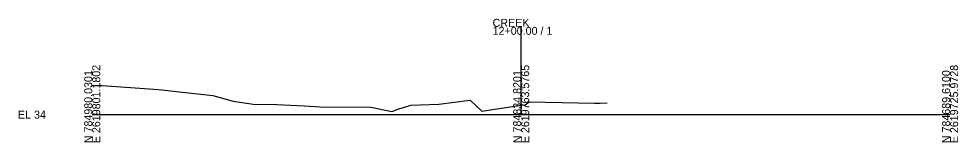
# Model space of a CAD drawing. Extents: x -26 to 303, y -10 to 5021.
# Drawn here: x -25.7 to 302.8, y 1490.3 to 1533.7 of the extents above; entities that cross this region are included whole.
import ezdxf

# ---------------------------------------------------------------- set-up
doc = ezdxf.new("R2010")
doc.units = 0
for name, color, linetype in [('RD_GPK_XS_Cell', 7, 'Continuous'), ('RD_XS_ExGround', 7, 'Continuous'), ('RD_XS_TX_Elev_EX', 7, 'Continuous')]:
    doc.layers.add(name, color=color, linetype=linetype)

msp = doc.modelspace()

# ---------------------------------------------------------------- linework, layer by layer
at = {"layer": 'RD_GPK_XS_Cell'}
for p, q in [((150, 1500), (150, 1530.82)), ((0, 1500), (150, 1500)), ((150, 1500), (300, 1500))]:
    msp.add_line(p, q, dxfattribs=at)
at = {"layer": 'RD_XS_ExGround'}
for p, q in [((0, 1510.27), (3.51, 1510.22)), ((3.51, 1510.22), (21.57, 1508.95)), ((21.57, 1508.95), (24.3, 1508.75)), ((24.3, 1508.75), (29.41, 1508.17)), ((29.41, 1508.17), (42.14, 1506.74)), ((42.14, 1506.74), (49.32, 1504.73)), ((49.32, 1504.73), (57.09, 1503.54)), ((121.25, 1503.7), (132.15, 1505.06)), ((132.15, 1505.06), (136.27, 1501.28)), ((57.09, 1503.54), (62.09, 1503.69)), ((62.09, 1503.69), (74.06, 1503.1)), ((74.06, 1503.1), (79.76, 1502.72)), ((79.76, 1502.72), (97.4, 1502.57)), ((97.4, 1502.57), (104.8, 1501.12)), ((104.8, 1501.12), (107.23, 1502.04)), ((107.23, 1502.04), (109.15, 1502.68)), ((109.15, 1502.68), (111.38, 1503.33)), ((111.38, 1503.33), (121.25, 1503.7)), ((136.27, 1501.28), (150, 1503.29)), ((150, 1503.29), (151.37, 1503.49)), ((151.37, 1503.49), (152.78, 1504.47)), ((152.78, 1504.47), (175.66, 1504.08)), ((175.66, 1504.08), (177.57, 1504.05)), ((177.57, 1504.05), (180.08, 1504.12))]:
    msp.add_line(p, q, dxfattribs=at)

# ---------------------------------------------------------------- texts
at = {"layer": 'RD_GPK_XS_Cell'}
for s, p in [('CREEK', (140, 1530.82)), ('12+00.00 / 1', (140, 1528.02)), ('EL 34', (-26, 1498.6))]:
    msp.add_text(s, height=2.8, dxfattribs=at).set_placement(p)
for s, p in [('N 784980.0301', (0, 1490)), ('E 2619801.1802', (2.8, 1490)), ('N 784834.8201', (150, 1490)), ('E 2619763.5765', (152.8, 1490)), ('N 784689.6100', (300, 1490)), ('E 2619725.9728', (302.8, 1490))]:
    msp.add_text(s, height=2.8, rotation=90, dxfattribs=at).set_placement(p)
at = {"layer": 'RD_XS_TX_Elev_EX'}
msp.add_text('37.29', height=0.8, rotation=90, dxfattribs=at).set_placement((150.7, 1508.29))

doc.saveas('drawing.dxf')
